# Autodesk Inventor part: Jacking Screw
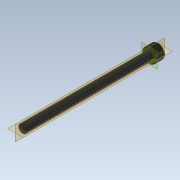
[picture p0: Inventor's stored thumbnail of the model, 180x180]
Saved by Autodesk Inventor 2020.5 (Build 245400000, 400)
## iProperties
LastFilename: FCG_Part.ipt
DataBaseUnit: MM
Created: 2023-06
Part Number: Jacking Screw
Material: 250 Grade
Document SubType Name: Modeling
Designer: A. Bennett
Mass: 23.6098 g
Surface Area: 20.844 cm^2
Volume: 2.93718 cm^3
Density: 8.03824 g/cm^3
Appearance: Gunmetal
Author: A. Bennett
Revision Number: -
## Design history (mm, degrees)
sketch "Sketch10"
  geometry: C1 r 5 at (0, 0); 1 further point
  constraints: 1 centre point, 1 coincident
  dimensions: "d25" = 10 diameter of C1
extrude "Extrusion7" new body sketch "Sketch10" distance "d26" = 6; taper "d27" = 0 deg
sketch "Sketch11"
  geometry: C1 r 3 at (0, 0); 1 further point
  constraints: 1 centre point, 1 coincident
  dimensions: "d28" = 6 diameter of C1
extrude "Extrusion8" join sketch "Sketch11" distance "d29" = 90; taper "d30" = 0 deg
chamfer "Chamfer1" distance "d31" = 0.5; stored, may be unused: second distance "d32" = 2, angle "d33" = 45 deg
fillet "Fillet2" dims "d34" = 0.25
thread "Thread1" dims "d35" = 89.5, "d36" = 0
sketch "Sketch12"
  geometry: C1 r 4.75 at (0, 0) reference; 2 further points
  constraints: 1 coincident
hole "Hole2" sketch "Sketch12" at (0, 0) diameter "d37" = 5; stored, may be unused: countersink angle "d41" = 90 deg, drill point angle "d43" = 118 deg; dims "d38" = 6, "d39" = 6, "d40" = 2, "d42" = 3
sketch "Sketch13"
  geometry: L1 (0, 2.887)-(2.5, 1.443); L2 (2.5, 1.443)-(2.5, -1.443); L3 (2.5, -1.443)-(0, -2.887); L4 (0, -2.887)-(-2.5, -1.443); L5 (-2.5, -1.443)-(-2.5, 1.443); L6 (-2.5, 1.443)-(0, 2.887); C1 r 4.75 at (0, 0) reference; 2 further points
  constraints: 12 end point, 1 coincident, 13 other
  dimensions: "d44" = 5 distance between parallel lines of L1 L4
extrude "Extrusion9" cut sketch "Sketch13" distance "d45" = 3; taper "d46" = 0 deg
body "Solid7"
other parameters: "OD" = 1 [user parameter], "OAL" = 1 [user parameter]
